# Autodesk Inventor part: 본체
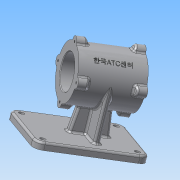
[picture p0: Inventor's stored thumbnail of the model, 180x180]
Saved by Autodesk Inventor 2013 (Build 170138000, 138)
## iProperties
Created: 2015-12
Part Number: 본체
Material: 알루미늄 6061
Document SubType Name: Modeling
Designer: Administrator
Density: 2.71 g/cm^3
Mass: 1165.53 g
Surface Area: 815.593 cm^2
Volume: 430.083 cm^3
Author: Administrator
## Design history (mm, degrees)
sketch "스케치1"
  geometry: L1 (-70, -55)-(70, -55); L2 (70, -55)-(70, 55); L3 (70, 55)-(-70, 55); L4 (-70, 55)-(-70, -55); L5 (-70, -55)-(70, 55); L6 (70, -55)-(-70, 55); 1 further point
  constraints: 12 end point, 2 midpoint, 2 parallel, 1 horizontal, 1 perpendicular
  dimensions: "d0" = 140 distance of L3.end L2.end; "d1" = 110 distance of L2.end L1.end
extrude "돌출1" new body sketch "스케치1" distance "d2" = 10; taper "d3" = 0 deg
node "작업 평면2"
sketch "스케치2"
  geometry: L1 (55, 0)-(-55, 0) reference; C1 r 37 at (0, 80); 2 further points
  constraints: 1 centre point, 1 midpoint, 1 vertical alignment
  dimensions: "d6" = 74 diameter of C1; "d8" = 80 distance from line of L1 C1.centre
extrude "돌출2" join sketch "스케치2" stored distance "d9" = 85; taper "d10" = 0 deg
sketch "스케치3"
  geometry: L1 (-52.5, 117)-(-52.5, 43) reference; L2 (32.5, 43)-(32.5, 117) reference; L3 (-52.5, 80)-(32.5, 80); L4 (-52.5, 103.5)-(-30.8, 103.5); L5 (-30.5, 103.2)-(-30.5, 101); L6 (-30.5, 101)-(10.5, 101); L7 (10.5, 101)-(10.5, 103.2); L8 (10.8, 103.5)-(32.5, 103.5); A1 r 0.3 centre (-30.8, 103.2) between (-30.5, 103.2) and (-30.8, 103.5); A2 r 0.3 centre (10.8, 103.2) between (10.8, 103.5) and (10.5, 103.2); 3 further points
  constraints: 12 end point, 6 point on line, 4 point on circle, 4 tangent, 3 parallel, 2 centre point, 2 collinear, 2 midpoint, 2 perpendicular, 1 equal radius
  dimensions: "d11" = 22 distance of L4.start point (-30.5, 103.5); "d13" = 22 distance of point (10.5, 103.5) L8.end; "d14" = 47 diameter of L8 L3; "d15" = 42 diameter of L6 L3; "d16" = 0.3 radius of A1
revolve "회전1" sketch "스케치3" stored, may be unused: angle "d17" = 90 deg
chamfer "모따기1" distance "d18" = 1; stored, may be unused: second distance "d19" = 2, angle "d20" = 45 deg
sketch "스케치4"
  geometry: L1 (70, 55)-(-70, 55) reference; L2 (-70, 55)-(-70, -55) reference; C1 r 4 at (-58, 43); C2 r 4 at (-58, -43); C3 r 4 at (58, -43); C4 r 4 at (58, 43); 1 further point
  constraints: 4 centre point, 2 horizontal alignment, 2 vertical alignment
  dimensions: "d21" = 8 diameter of C1; "d22" = 8 diameter of C2; "d23" = 8 diameter of C3; "d24" = 8 diameter of C4; "d25" = 12 distance from line of L1 C1.centre; "d26" = 12 distance from line of L2 C1.centre; "d27" = 116 distance of C4.centre C1.centre; "d28" = 86 distance of C1.centre C2.centre
extrude "돌출3" cut sketch "스케치4" stored distance "d29" = 85; taper "d30" = 0 deg
node "작업 평면3"
sketch "스케치5"
  geometry: L1 (0, 37)-(-70, 37); L2 (-70, -55)-(-70, 55) reference; L3 (0, -37)-(-70, -37); L4 (-70, 37)-(-70, -37); A1 r 37 centre (0, 0) between (0, 37) and (0, -37) reference; A2 r 37 centre (0, 0) between (0, 37) and (0, -37); 1 further point
  constraints: 6 end point, 4 point on circle, 2 point on line, 1 centre point, 1 coincident, 1 concentric, 1 horizontal, 1 parallel, 1 perpendicular, 1 tangent, 1 vertical alignment
sketch "스케치7"
  geometry: L1 (70, 10)-(-70, 10) reference; L2 (32.5, 43)-(-52.5, 43) reference; L3 (15, 10)-(10, 50.722); L4 (10, 50.722)-(-30, 50.722); L5 (-30, 50.722)-(-35, 10); L6 (-35, 10)-(15, 10); 3 further points
  constraints: 8 end point, 2 midpoint, 2 parallel, 2 point on line, 1 equal length, 1 vertical alignment
  dimensions: "d40" = 97 deg angle of L1 L5; "d41" = 50 distance of L3.start L5.end; "d43" = 40 distance of L3.end L4.end
sketch "스케치8"
  geometry: A1 r 37 centre (0, 0) between (-37, 0) and (-36.338, -6.969) reference; A2 r 7 centre (-37, 0) between (-36.338, 6.969) and (-36.338, -6.969); 1 further point
  constraints: 5 point on circle, 1 centre point, 1 horizontal alignment
  dimensions: "d46" = 14 diameter of A2
extrude "돌출6" join sketch "스케치8" distance "d47" = 15; taper "d48" = 0 deg
node "작업 평면4"
sketch "스케치11"
  geometry: L1 (10.5, 101)-(10.5, 59) reference; L2 (-30.5, 101)-(-30.5, 59) reference; L3 (-30.5, 80)-(10.5, 80); L4 (17.5, 117)-(-37.5, 117) reference; L5 (-52.5, 124)-(-37.5, 124) reference; L6 (17.5, 124)-(32.5, 124) reference; L7 (-37.5, 117)-(-40.048, 124); L8 (-40.048, 124)-(20.048, 124); L9 (17.5, 117)-(20.048, 124); L10 (17.5, 116.338)-(17.5, 124) reference; L11 (17.5, 117)-(-37.5, 117); 1 further point
  constraints: 10 end point, 2 midpoint, 2 point on line, 1 collinear
  dimensions: "d55" = 110 deg angle of L11 L7; "d56" = 110 deg angle of L4 L9
revolve "회전2" sketch "스케치11" stored, may be unused: angle "d57" = 90 deg
hole "구멍1" diameter "d60" = 3.242; stored, may be unused: countersink angle "d64" = 90 deg, drill point angle "d66" = 118 deg; dims "d58" = 10, "d59" = 10, "d61" = 9, "d62" = 4, "d63" = 2, "d65" = 11
node "작업 평면5"
fillet "모깎기1" dims "d70" = 12
extrude "돌출7" join sketch "스케치7" stored distance "d71" = 12; taper "d72" = 0 deg
extrude "돌출8" join sketch "스케치5" stored distance "d73" = 8; taper "d74" = 0 deg
fillet "모깎기2" dims "d75" = 3
fillet "모깎기3" dims "d76" = 3
fillet "모깎기4" dims "d77" = 3
fillet "모깎기5" dims "d78" = 3
fillet "모깎기6" dims "d79" = 3
fillet "모깎기7" dims "d80" = 3
fillet "모깎기8" dims "d81" = 3
sketch "스케치12"
  geometry: L1 (-106.163, -26.163)-(-80, 0); L2 (-10, 43)-(-10, -43) reference; C1 r 1.621 at (-43, 0) reference; C2 r 1.621 at (-80, -37) reference; C3 r 1.621 at (-117, 0) reference; C4 r 1.621 at (-80, 37) reference; C5 r 24.5 at (-80, 0) reference; A1 r 37 centre (-80, 0) between (-115.862, -9.104) and (-89.104, -35.863) reference; A2 r 3 centre (-89.842, -38.77) between (-86.889, -38.239) and (-89.104, -35.863) reference; A3 r 7 centre (-80, -37) between (-86.889, -38.239) and (-73.111, -38.239) reference; A4 r 3 centre (-70.158, -38.77) between (-70.896, -35.863) and (-73.111, -38.239) reference; A5 r 37 centre (-80, 0) between (-70.896, -35.863) and (-44.138, -9.104) reference; A6 r 3 centre (-41.23, -9.842) between (-41.761, -6.889) and (-44.138, -9.104) reference; A7 r 7 centre (-43, 0) between (-41.761, -6.889) and (-41.761, 6.889) reference; A8 r 3 centre (-41.23, 9.842) between (-44.138, 9.104) and (-41.761, 6.889) reference; A9 r 37 centre (-80, 0) between (-44.138, 9.104) and (-70.896, 35.863) reference; A10 r 3 centre (-70.158, 38.77) between (-73.111, 38.239) and (-70.896, 35.863) reference; A11 r 7 centre (-80, 37) between (-73.111, 38.239) and (-86.889, 38.239) reference; A12 r 3 centre (-89.842, 38.77) between (-89.104, 35.863) and (-86.889, 38.239) reference; A13 r 37 centre (-80, 0) between (-89.104, 35.863) and (-115.862, 9.104) reference; A14 r 3 centre (-118.77, 9.842) between (-118.239, 6.889) and (-115.862, 9.104) reference; A15 r 7 centre (-117, 0) between (-118.239, 6.889) and (-118.239, -6.889) reference; A16 r 3 centre (-118.77, -9.842) between (-115.862, -9.104) and (-118.239, -6.889) reference; 1 further point
  constraints: 2 end point, 1 point on circle
  dimensions: "d82" = 45 deg angle of L2 L1
node "작업 평면6"
sketch "스케치13"
  geometry: L1 (-85, 18.921)-(-85, -18.921) reference; 3 further points
  constraints: 1 horizontal alignment, 1 midpoint, 1 other
  dimensions: "d83" = 42.5 distance from line of L1 point (-42.5, 0)
feature "엠보싱1" sketch "스케치13" dims "d84" = 0.5, "d85" = 0
node "솔리드1"
pattern_circular "원형 패턴1" dims angle "d53" = 360 deg
mirror "대칭1"
pattern_circular "원형 패턴2" dims angle "d68" = 360 deg
mirror "대칭2"
